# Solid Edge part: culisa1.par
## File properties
Author: Ionut
Template: Normal.par
Last saved by: Ionut
Revision: 2
Application: Solid Edge
Density: 7800.000 kg/m^3
Accuracy: 0.010
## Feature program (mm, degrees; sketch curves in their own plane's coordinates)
sketch for "unnamed Protrusion 1" plane through (0, 0, 0) normal (0, 0, 1) x-axis (1, 0, 0)
  line (-12, -40) -> (0, -40)
  line (0, -40) -> (0, 40)
  line (0, 40) -> (-12, 40)
  line (-12, 40) -> (-12, -40)
  dimension (linear) = 12
extrude "unnamed Protrusion 1" add finite 3 along +normal
sketch for "ExtrudedCutout_1" plane through (-6, 0, 3) normal (0, 0, 1) x-axis (0, 1, 0)
  circle centre (34, 0) radius 2
  dimension (linear) = 34
extrude "ExtrudedCutout_1" cut finite 71.1104 along -normal
sketch for "ExtrudedCutout_2" plane through (-6, 0, 3) normal (0, 0, 1) x-axis (0, 1, 0)
  line (-28, -2) -> (22, -2)
  line (22, -2) -> (22, 2)
  line (22, 2) -> (-28, 2)
  line (-28, 2) -> (-28, -2)
  dimension (linear) = 22
  dimension (linear) = 28
  dimension (linear) = 22
extrude "ExtrudedCutout_2" cut finite 50.3452 along -normal
fillet "Round_1" radius 2
fillet "Round_2" radius 6
sketch for "ExtrudedProtrusion_2" plane through (-6, 0, 3) normal (0, 0, 1) x-axis (0, 1, 0)
extrude "ExtrudedProtrusion_2" add finite 3 along +normal
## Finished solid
Body 1: solid body, 13 faces, 28 edges, 16 vertices.
  Faces by surface: plane 7, cylinder 6
  Edges by curve: line 16, circle 12
Bounding box of the edges (mm): 12.000 x 80.000 x 6.000, from (-12, -40, 0) to (0, 40, 6).
Cylindrical faces by radius (mm): R2 x4, R6 x2
Planar faces by outward normal: +x 2, +z 2, -x 2, -z 1
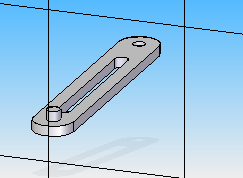
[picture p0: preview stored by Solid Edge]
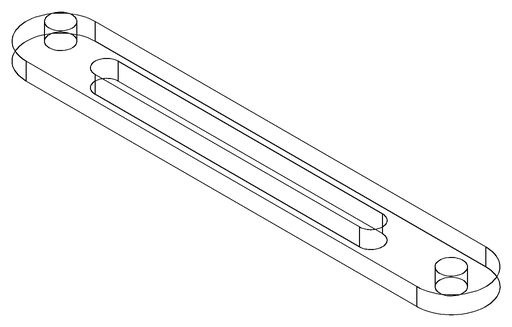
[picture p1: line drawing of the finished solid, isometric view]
